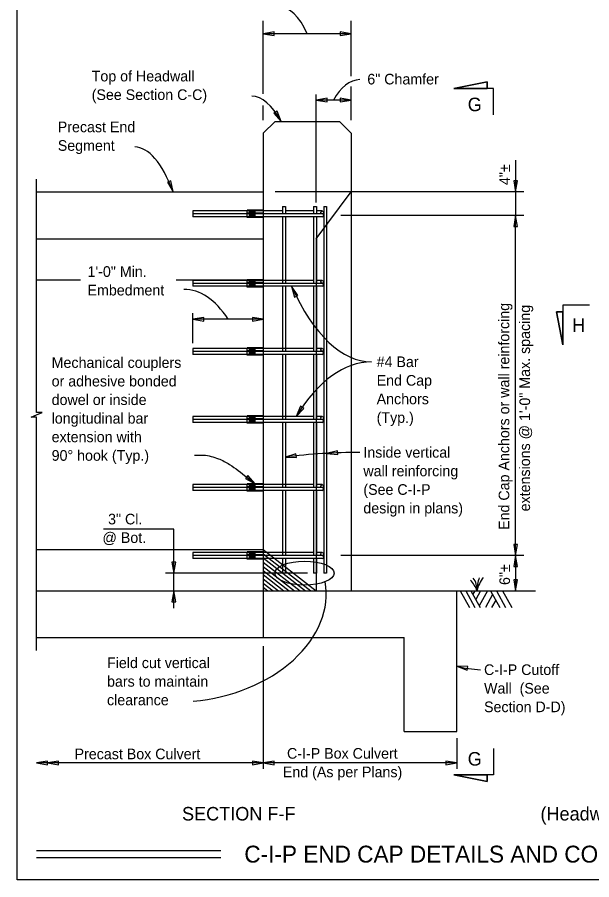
# Model space of a CAD drawing. Extents: x 0 to 30.8, y 0 to 19.8.
# Drawn here: x 0 to 8.16, y 0 to 12.25 of the extents above; entities that cross this region are included whole.
import ezdxf

# ---------------------------------------------------------------- set-up
doc = ezdxf.new("R2010")
doc.units = 0
for name, color, linetype in [('Dimension', 7, 'Continuous'), ('Miscellaneous', 7, 'Continuous'), ('Miscellaneous1', 7, 'Continuous'), ('Rebar', 7, 'Continuous'), ('SubStrConc', 7, 'Continuous'), ('SubStrConc_h', 7, 'Continuous'), ('TextStructures', 7, 'Continuous')]:
    doc.layers.add(name, color=color, linetype=linetype)

msp = doc.modelspace()

# ---------------------------------------------------------------- linework, layer by layer
at = {"layer": 'Dimension'}
for p, q in [((3.497, 11.165), (3.497, 12.205)), ((4.747, 11.419), (4.747, 12.205)), ((4.747, 12.021), (3.497, 12.021)), ((6.207, 11.244), (6.676, 11.338)), ((6.676, 11.338), (6.676, 11.244)), ((4.247, 9.625), (4.247, 11.159)), ((4.747, 10.791), (4.747, 11.27)), ((6.77, 11.244), (6.207, 11.244)), ((6.77, 10.869), (6.77, 11.244)), ((4.747, 11.078), (4.247, 11.078)), ((3.497, 10.791), (3.497, 11)), ((7.082, 10.226), (7.082, 9.773)), ((7.2, 9.773), (3.666, 9.773)), ((7.082, 9.773), (7.082, 9.44)), ((7.2, 9.44), (4.599, 9.44)), ((7.082, 4.607), (7.082, 9.44)), ((8.131, 8.162), (7.756, 8.162)), ((7.756, 8.162), (7.756, 7.6)), ((2.497, 7.625), (2.497, 8.052)), ((7.756, 7.6), (7.662, 8.068)), ((7.662, 8.068), (7.756, 8.068)), ((3.497, 7.965), (2.497, 7.965)), ((2.225, 4.982), (1.228, 4.982)), ((2.225, 4.357), (2.225, 4.982)), ((7.2, 4.607), (4.599, 4.607)), ((7.082, 4.607), (7.082, 4.107)), ((4.124, 4.357), (2.109, 4.357)), ((2.225, 4.107), (2.225, 4.357)), ((2.225, 3.857), (2.225, 4.107)), ((3.497, 3.319), (3.497, 1.578)), ((6.247, 2.013), (6.247, 1.578)), ((6.77, 1.865), (6.77, 1.49)), ((3.497, 1.661), (0.275, 1.661)), ((6.247, 1.661), (3.497, 1.661)), ((6.77, 1.49), (6.207, 1.49)), ((6.207, 1.49), (6.676, 1.396)), ((6.676, 1.396), (6.676, 1.49)), ((0.275, 0.414), (2.892, 0.414)), ((0.275, 0.314), (2.892, 0.314))]:
    msp.add_line(p, q, dxfattribs=at)
for points in [[(3.497, 12.02), (3.653, 11.994), (3.653, 12.047)], [(4.747, 12.02), (4.591, 12.047), (4.591, 11.994)], [(6.676, 11.244), (6.676, 11.338), (6.207, 11.244)], [(4.247, 11.078), (4.403, 11.051), (4.403, 11.104)], [(4.747, 11.078), (4.591, 11.104), (4.591, 11.051)], [(3.752, 10.773), (3.692, 10.92), (3.647, 10.892)], [(2.215, 9.773), (2.184, 9.929), (2.135, 9.91)], [(7.082, 9.773), (7.109, 9.93), (7.056, 9.93)], [(7.082, 9.44), (7.056, 9.284), (7.109, 9.284)], [(3.897, 8.432), (3.941, 8.279), (3.988, 8.302)], [(2.497, 7.965), (2.653, 7.938), (2.653, 7.991)], [(3.497, 7.965), (3.341, 7.991), (3.341, 7.938)], [(7.756, 8.068), (7.662, 8.068), (7.756, 7.6)], [(3.964, 6.582), (4.071, 6.698), (4.026, 6.727)], [(3.81, 6.004), (3.968, 5.998), (3.961, 6.05)], [(4.397, 6.058), (4.554, 6.04), (4.551, 6.093)], [(3.382, 5.625), (3.276, 5.743), (3.243, 5.701)], [(7.082, 4.607), (7.109, 4.763), (7.056, 4.763)], [(7.082, 4.607), (7.056, 4.451), (7.109, 4.451)], [(2.225, 4.357), (2.252, 4.513), (2.199, 4.513)], [(7.082, 4.107), (7.109, 4.263), (7.056, 4.263)], [(2.225, 4.107), (2.199, 3.951), (2.252, 3.951)], [(6.247, 3.036), (6.395, 2.978), (6.405, 3.03)], [(0.275, 1.661), (0.431, 1.634), (0.431, 1.687)], [(0.431, 1.661), (0.587, 1.634), (0.587, 1.687)], [(3.497, 1.66), (3.341, 1.687), (3.341, 1.634)], [(3.497, 1.66), (3.653, 1.634), (3.653, 1.687)], [(6.247, 1.66), (6.091, 1.687), (6.091, 1.634)], [(6.676, 1.49), (6.676, 1.396), (6.207, 1.49)]]:
    msp.add_lwpolyline(points, close=True, dxfattribs=at)
msp.add_lwpolyline([(0.275, 3.259), (0.275, 6.573), (0.197, 6.573), (0.275, 6.607), (0.352, 6.641), (0.275, 6.641), (0.275, 9.954)], dxfattribs=at)
for centre, radius, start, end in [((4.824, -1.734), 7.804, 89.6845, 97.4662), ((6.723, 4.952), 1.975, 256.0571, 265.9161)]:
    msp.add_arc(centre, radius, start, end, dxfattribs=at)
for centre, major_axis, ratio, start_param, end_param in [((3.768, 10.977), (0.045, -1.424), 0.393454, 2.379989, 3.141593), ((4.904, 10.391), (0.035, -0.978), 0.560741, 3.141593, 3.913766), ((3.249, 7.176), (-0.084, -3.958), 0.261149, 2.716835, 3.141593), ((1.586, 6.454), (-0.084, -3.958), 0.261149, 2.571065, 3.141593), ((2.421, 6.457), (0.052, -1.93), 0.503079, 2.454108, 3.141593), ((5.002, 11.557), (-0.033, 4.197), 0.40152, 2.407456, 3.141215), ((5.062, 3.46), (0.027, -3.9), 0.462577, 3.141946, 3.780946), ((2.532, 3.88), (-1.843, -0.35), 0.707446, 1.420997, 3.145082)]:
    msp.add_ellipse(centre, major_axis=major_axis, ratio=ratio, start_param=start_param, end_param=end_param, dxfattribs=at)
msp.add_ellipse((4.083, 4.357), major_axis=(0.421, 0), ratio=0.404515, dxfattribs=at)
msp.add_spline([(2.519, 6.033), (2.648, 6.033), (2.859, 5.982), (3.017, 5.901), (3.14, 5.816), (3.382, 5.625)], degree=3, dxfattribs=at)
at = {"layer": 'Miscellaneous'}
for p, q in [((3.497, 9.513), (3.268, 9.513)), ((3.497, 9.471), (3.268, 9.471)), ((3.34, 9.503), (3.3, 9.503)), ((3.3, 9.471), (3.3, 9.503)), ((3.34, 9.461), (3.3, 9.461)), ((3.3, 9.419), (3.3, 9.461)), ((3.34, 9.461), (3.3, 9.461)), ((3.31, 9.471), (3.31, 9.503)), ((3.31, 9.419), (3.31, 9.461)), ((3.32, 9.471), (3.32, 9.503)), ((3.32, 9.419), (3.32, 9.461)), ((3.33, 9.471), (3.33, 9.503)), ((3.33, 9.419), (3.33, 9.461)), ((3.38, 9.503), (3.34, 9.503)), ((3.34, 9.471), (3.34, 9.503)), ((3.38, 9.461), (3.34, 9.461)), ((3.34, 9.419), (3.34, 9.461)), ((3.38, 9.461), (3.34, 9.461)), ((3.35, 9.471), (3.35, 9.503)), ((3.35, 9.419), (3.35, 9.461)), ((3.36, 9.471), (3.36, 9.503)), ((3.36, 9.419), (3.36, 9.461)), ((3.37, 9.471), (3.37, 9.503)), ((3.37, 9.419), (3.37, 9.461)), ((3.38, 9.471), (3.38, 9.503)), ((3.38, 9.419), (3.38, 9.461)), ((3.497, 9.409), (3.268, 9.409)), ((3.34, 9.419), (3.3, 9.419)), ((3.38, 9.419), (3.34, 9.419)), ((3.497, 8.525), (3.268, 8.525)), ((3.497, 8.484), (3.268, 8.484)), ((3.34, 8.515), (3.3, 8.515)), ((3.3, 8.484), (3.3, 8.515)), ((3.34, 8.474), (3.3, 8.474)), ((3.3, 8.432), (3.3, 8.474)), ((3.34, 8.473), (3.3, 8.473)), ((3.31, 8.484), (3.31, 8.515)), ((3.31, 8.432), (3.31, 8.474)), ((3.32, 8.484), (3.32, 8.515)), ((3.32, 8.432), (3.32, 8.474)), ((3.33, 8.484), (3.33, 8.515)), ((3.33, 8.432), (3.33, 8.474)), ((3.38, 8.515), (3.34, 8.515)), ((3.34, 8.484), (3.34, 8.515)), ((3.38, 8.474), (3.34, 8.474)), ((3.34, 8.432), (3.34, 8.474)), ((3.38, 8.473), (3.34, 8.473)), ((3.35, 8.484), (3.35, 8.515)), ((3.35, 8.432), (3.35, 8.474)), ((3.36, 8.484), (3.36, 8.515)), ((3.36, 8.432), (3.36, 8.474)), ((3.37, 8.484), (3.37, 8.515)), ((3.37, 8.432), (3.37, 8.474)), ((3.38, 8.484), (3.38, 8.515)), ((3.38, 8.432), (3.38, 8.474)), ((3.497, 8.422), (3.268, 8.422)), ((3.34, 8.432), (3.3, 8.432)), ((3.38, 8.432), (3.34, 8.432)), ((3.497, 7.559), (3.268, 7.559)), ((3.497, 7.517), (3.268, 7.517)), ((3.34, 7.549), (3.3, 7.549)), ((3.3, 7.517), (3.3, 7.549)), ((3.34, 7.507), (3.3, 7.507)), ((3.3, 7.465), (3.3, 7.507)), ((3.34, 7.507), (3.3, 7.507)), ((3.31, 7.517), (3.31, 7.549)), ((3.31, 7.465), (3.31, 7.507)), ((3.32, 7.517), (3.32, 7.549)), ((3.32, 7.465), (3.32, 7.507)), ((3.33, 7.517), (3.33, 7.549)), ((3.33, 7.465), (3.33, 7.507)), ((3.38, 7.549), (3.34, 7.549)), ((3.34, 7.517), (3.34, 7.549)), ((3.38, 7.507), (3.34, 7.507)), ((3.34, 7.465), (3.34, 7.507)), ((3.38, 7.507), (3.34, 7.507)), ((3.35, 7.517), (3.35, 7.549)), ((3.35, 7.465), (3.35, 7.507)), ((3.36, 7.517), (3.36, 7.549)), ((3.36, 7.465), (3.36, 7.507)), ((3.37, 7.517), (3.37, 7.549)), ((3.37, 7.465), (3.37, 7.507)), ((3.38, 7.517), (3.38, 7.549)), ((3.38, 7.465), (3.38, 7.507)), ((3.497, 7.455), (3.268, 7.455)), ((3.34, 7.465), (3.3, 7.465)), ((3.38, 7.465), (3.34, 7.465)), ((3.497, 6.592), (3.268, 6.592)), ((3.497, 6.55), (3.268, 6.55)), ((3.34, 6.582), (3.3, 6.582)), ((3.3, 6.55), (3.3, 6.582)), ((3.34, 6.54), (3.3, 6.54)), ((3.3, 6.499), (3.3, 6.54)), ((3.34, 6.54), (3.3, 6.54)), ((3.34, 6.499), (3.3, 6.499)), ((3.31, 6.55), (3.31, 6.582)), ((3.31, 6.499), (3.31, 6.54)), ((3.32, 6.55), (3.32, 6.582)), ((3.32, 6.499), (3.32, 6.54)), ((3.33, 6.55), (3.33, 6.582)), ((3.33, 6.499), (3.33, 6.54)), ((3.38, 6.582), (3.34, 6.582)), ((3.34, 6.55), (3.34, 6.582)), ((3.38, 6.54), (3.34, 6.54)), ((3.34, 6.499), (3.34, 6.54)), ((3.38, 6.54), (3.34, 6.54)), ((3.38, 6.499), (3.34, 6.499)), ((3.35, 6.55), (3.35, 6.582)), ((3.35, 6.499), (3.35, 6.54)), ((3.36, 6.55), (3.36, 6.582)), ((3.36, 6.499), (3.36, 6.54)), ((3.37, 6.55), (3.37, 6.582)), ((3.37, 6.499), (3.37, 6.54)), ((3.38, 6.55), (3.38, 6.582)), ((3.38, 6.499), (3.38, 6.54)), ((3.497, 6.488), (3.268, 6.488)), ((3.497, 5.625), (3.268, 5.625)), ((3.497, 5.584), (3.268, 5.584)), ((3.497, 5.522), (3.268, 5.522)), ((3.34, 5.615), (3.3, 5.615)), ((3.3, 5.584), (3.3, 5.615)), ((3.34, 5.574), (3.3, 5.574)), ((3.3, 5.532), (3.3, 5.574)), ((3.34, 5.573), (3.3, 5.573)), ((3.34, 5.532), (3.3, 5.532)), ((3.31, 5.584), (3.31, 5.615)), ((3.31, 5.532), (3.31, 5.574)), ((3.32, 5.584), (3.32, 5.615)), ((3.32, 5.532), (3.32, 5.574)), ((3.33, 5.584), (3.33, 5.615)), ((3.33, 5.532), (3.33, 5.574)), ((3.38, 5.615), (3.34, 5.615)), ((3.34, 5.584), (3.34, 5.615)), ((3.38, 5.574), (3.34, 5.574)), ((3.34, 5.532), (3.34, 5.574)), ((3.38, 5.573), (3.34, 5.573)), ((3.38, 5.532), (3.34, 5.532)), ((3.35, 5.584), (3.35, 5.615)), ((3.35, 5.532), (3.35, 5.574)), ((3.36, 5.584), (3.36, 5.615)), ((3.36, 5.532), (3.36, 5.574)), ((3.37, 5.584), (3.37, 5.615)), ((3.37, 5.532), (3.37, 5.574)), ((3.38, 5.584), (3.38, 5.615)), ((3.38, 5.532), (3.38, 5.574)), ((3.497, 4.659), (3.268, 4.659)), ((3.497, 4.617), (3.268, 4.617)), ((3.497, 4.555), (3.268, 4.555)), ((3.34, 4.649), (3.3, 4.649)), ((3.3, 4.617), (3.3, 4.649)), ((3.34, 4.607), (3.3, 4.607)), ((3.3, 4.565), (3.3, 4.607)), ((3.34, 4.607), (3.3, 4.607)), ((3.34, 4.565), (3.3, 4.565)), ((3.31, 4.617), (3.31, 4.649)), ((3.31, 4.565), (3.31, 4.607)), ((3.32, 4.617), (3.32, 4.649)), ((3.32, 4.565), (3.32, 4.607)), ((3.33, 4.617), (3.33, 4.649)), ((3.33, 4.565), (3.33, 4.607)), ((3.38, 4.649), (3.34, 4.649)), ((3.34, 4.617), (3.34, 4.649)), ((3.38, 4.607), (3.34, 4.607)), ((3.34, 4.565), (3.34, 4.607)), ((3.38, 4.607), (3.34, 4.607)), ((3.38, 4.565), (3.34, 4.565)), ((3.35, 4.617), (3.35, 4.649)), ((3.35, 4.565), (3.35, 4.607)), ((3.36, 4.617), (3.36, 4.649)), ((3.36, 4.565), (3.36, 4.607)), ((3.37, 4.617), (3.37, 4.649)), ((3.37, 4.565), (3.37, 4.607)), ((3.38, 4.617), (3.38, 4.649)), ((3.38, 4.565), (3.38, 4.607)), ((6.247, 4.107), (7.366, 4.107)), ((6.296, 4.107), (6.427, 3.867)), ((6.374, 4.107), (6.505, 3.867)), ((6.448, 4.107), (6.579, 3.867)), ((6.503, 4.107), (6.476, 4.057)), ((6.583, 4.107), (6.516, 3.984)), ((6.683, 4.107), (6.565, 3.893)), ((6.756, 4.054), (6.654, 3.867)), ((6.727, 4.107), (6.859, 3.867)), ((6.81, 4.107), (6.941, 3.867)), ((6.898, 4.107), (7.03, 3.867)), ((6.8, 3.973), (6.742, 3.867))]:
    msp.add_line(p, q, dxfattribs=at)
for points in [[(3.268, 9.471), (3.268, 9.513)], [(3.268, 9.409), (3.268, 9.471)], [(3.268, 8.484), (3.268, 8.525)], [(3.268, 8.422), (3.268, 8.484)], [(3.268, 7.517), (3.268, 7.559)], [(3.268, 7.455), (3.268, 7.517)], [(3.268, 6.55), (3.268, 6.592)], [(3.268, 6.488), (3.268, 6.55)], [(3.268, 5.584), (3.268, 5.625)], [(3.268, 5.522), (3.268, 5.584)], [(3.268, 4.617), (3.268, 4.659)], [(3.268, 4.555), (3.268, 4.617)]]:
    msp.add_lwpolyline(points, dxfattribs=at)
for centre, radius, start, end in [((7.096, 3.956), 0.584, 144.3747, 165.0402), ((6.935, 4.127), 0.403, 155.9437, 182.9219), ((6.205, 4.007), 0.342, 16.9178, 46.7762), ((6.261, 4.126), 0.272, 356.0505, 36.015)]:
    msp.add_arc(centre, radius, start, end, dxfattribs=at)
at = {"layer": 'Miscellaneous1'}
msp.add_lwpolyline([(0, 19.8), (30.8, 19.8), (30.8, 0), (0, 0)], close=True, dxfattribs=at)
at = {"layer": 'Rebar'}
for p, q in [((3.768, 9.565), (3.768, 9.461)), ((3.768, 9.565), (3.81, 9.565)), ((3.81, 9.565), (3.81, 9.461)), ((4.21, 9.565), (4.21, 9.461)), ((4.21, 9.565), (4.251, 9.565)), ((4.251, 9.565), (4.251, 9.461)), ((4.355, 9.565), (4.397, 9.565)), ((4.355, 9.565), (4.355, 4.357)), ((4.397, 9.565), (4.397, 4.357)), ((2.497, 9.503), (2.497, 9.419)), ((3.768, 9.503), (2.497, 9.503)), ((4.334, 9.461), (2.497, 9.461)), ((4.21, 9.503), (3.81, 9.503)), ((4.334, 9.503), (4.251, 9.503)), ((4.334, 9.419), (2.497, 9.419)), ((3.768, 9.419), (3.768, 8.473)), ((3.81, 9.417), (3.81, 8.473)), ((4.21, 9.419), (4.21, 8.474)), ((4.251, 9.417), (4.251, 8.474)), ((2.497, 8.515), (2.497, 8.432)), ((4.21, 8.515), (2.497, 8.515)), ((4.334, 8.474), (2.497, 8.474)), ((4.334, 8.515), (4.251, 8.515)), ((4.334, 8.432), (2.497, 8.432)), ((3.768, 8.432), (3.768, 7.507)), ((3.81, 8.432), (3.81, 7.507)), ((4.21, 8.432), (4.21, 7.507)), ((4.251, 8.432), (4.251, 7.507)), ((2.497, 7.548), (2.497, 7.465)), ((4.21, 7.548), (2.497, 7.548)), ((4.334, 7.507), (2.497, 7.507)), ((4.334, 7.548), (4.251, 7.548)), ((4.334, 7.465), (2.497, 7.465)), ((3.768, 7.465), (3.768, 6.54)), ((3.81, 7.465), (3.81, 6.54)), ((4.21, 7.465), (4.21, 6.54)), ((4.251, 7.465), (4.251, 6.54)), ((2.497, 6.582), (2.497, 6.499)), ((4.21, 6.582), (2.497, 6.582)), ((4.334, 6.54), (2.497, 6.54)), ((4.334, 6.499), (2.497, 6.499)), ((3.768, 6.499), (3.768, 5.573)), ((3.81, 6.499), (3.81, 5.573)), ((4.21, 6.499), (4.21, 5.574)), ((4.334, 6.582), (4.251, 6.582)), ((4.251, 6.499), (4.251, 5.574)), ((2.497, 5.615), (2.497, 5.532)), ((4.21, 5.615), (2.497, 5.615)), ((4.334, 5.574), (2.497, 5.574)), ((4.334, 5.532), (2.497, 5.532)), ((3.768, 5.532), (3.768, 4.607)), ((3.81, 5.532), (3.81, 4.607)), ((4.21, 5.532), (4.21, 4.607)), ((4.334, 5.615), (4.251, 5.615)), ((4.251, 5.532), (4.251, 4.607)), ((2.497, 4.648), (2.497, 4.565)), ((4.21, 4.648), (2.497, 4.648)), ((4.334, 4.607), (2.497, 4.607)), ((4.334, 4.565), (2.497, 4.565)), ((3.768, 4.565), (3.768, 4.357)), ((3.81, 4.565), (3.81, 4.357)), ((4.21, 4.565), (4.21, 4.357)), ((4.334, 4.648), (4.251, 4.648)), ((4.251, 4.565), (4.251, 4.357)), ((3.81, 4.357), (3.768, 4.357)), ((4.251, 4.357), (4.21, 4.357)), ((4.397, 4.357), (4.355, 4.357))]:
    msp.add_line(p, q, dxfattribs=at)
for centre in [(4.334, 9.482), (4.334, 8.494), (4.334, 7.528), (4.334, 6.561), (4.334, 5.594), (4.334, 4.628)]:
    msp.add_circle(centre, 0.0208, dxfattribs=at)
for centre in [(4.334, 9.44), (4.334, 8.453), (4.334, 7.486), (4.334, 6.519), (4.334, 5.553), (4.334, 4.586)]:
    msp.add_arc(centre, 0.0208, 270, 90, dxfattribs=at)
at = {"layer": 'SubStrConc'}
for p, q in [((3.664, 10.773), (3.497, 10.607)), ((3.664, 10.773), (4.58, 10.773)), ((4.747, 10.607), (4.58, 10.773)), ((3.497, 10.607), (3.497, 4.107)), ((4.747, 10.607), (4.747, 4.107)), ((4.247, 9.107), (4.747, 9.773)), ((4.247, 9.107), (4.247, 4.107)), ((3.497, 4.69), (4.247, 4.107)), ((3.497, 4.631), (4.171, 4.107)), ((3.497, 4.572), (4.095, 4.107)), ((3.497, 4.512), (4.019, 4.107)), ((3.497, 4.453), (3.942, 4.107)), ((3.497, 4.394), (3.866, 4.107)), ((3.497, 4.335), (3.79, 4.107)), ((3.497, 4.275), (3.714, 4.107)), ((3.497, 4.216), (3.638, 4.107)), ((3.497, 4.157), (3.561, 4.107)), ((3.497, 4.107), (4.747, 4.107))]:
    msp.add_line(p, q, dxfattribs=at)
at = {"layer": 'SubStrConc_h'}
for p, q in [((0.275, 9.773), (3.497, 9.773)), ((0.275, 9.107), (3.497, 9.107)), ((0.275, 8.524), (0.898, 8.524)), ((2.259, 8.524), (3.497, 8.524)), ((0.275, 4.69), (3.497, 4.69)), ((0.275, 4.107), (3.497, 4.107)), ((3.497, 4.107), (3.497, 3.44)), ((4.747, 4.107), (6.247, 4.107)), ((6.247, 2.107), (6.247, 4.107)), ((0.275, 3.44), (5.497, 3.44)), ((5.497, 2.107), (5.497, 3.44)), ((5.497, 2.107), (6.247, 2.107))]:
    msp.add_line(p, q, dxfattribs=at)
at = {"layer": 'TextStructures'}
msp.add_lwpolyline([(0, 19.477), (30.8, 19.477), (30.8, 0), (0, 0)], close=True, dxfattribs=at)

# ---------------------------------------------------------------- texts
at = {"layer": 'Dimension'}
for s, p in [('Top of Headwall', (1.058, 11.343)), ('(See Section C-C)', (1.058, 11.079)), ('Precast End', (0.576, 10.621)), ('Segment', (0.576, 10.357)), ('1\'-0" Min.', (0.999, 8.566)), ('Embedment', (0.999, 8.302)), ('Mechanical couplers', (0.489, 7.273)), ('#4 Bar', (5.108, 7.284)), ('or adhesive bonded', (0.489, 7.009)), ('End Cap', (5.108, 7.02)), ('dowel or inside', (0.489, 6.745)), ('Anchors', (5.108, 6.756)), ('longitudinal bar', (0.489, 6.481)), ('(Typ.)', (5.108, 6.492)), ('extension with', (0.489, 6.217)), ('Inside vertical', (4.919, 5.997)), ('90° hook (Typ.)', (0.489, 5.953)), ('wall reinforcing', (4.919, 5.733)), ('(See C-I-P', (4.919, 5.469)), ('design in plans)', (4.919, 5.205)), ('3" Cl.', (1.291, 5.049)), ('@ Bot.', (1.211, 4.785)), ('Field cut vertical', (1.276, 3.007)), ('C-I-P Cutoff', (6.634, 2.909)), ('bars to maintain', (1.276, 2.743)), ('Wall  (See', (6.634, 2.645)), ('clearance', (1.276, 2.479)), ('Section D-D)', (6.634, 2.381)), ('C-I-P Box Culvert', (3.834, 1.72)), ('End (As per Plans)', (3.775, 1.456))]:
    msp.add_text(s, height=0.1512, dxfattribs=at).set_placement(p)
for s, p in [('End Cap Anchors or wall reinforcing', (6.993, 4.971)), ('extensions @ 1\'-0" Max. spacing', (7.288, 5.234))]:
    msp.add_text(s, height=0.1512, rotation=90, dxfattribs=at).set_placement(p)
at = {"layer": 'TextStructures'}
for s, height, p in [('6" Chamfer', 0.1512, (4.975, 11.3)), ('G', 0.192, (6.402, 10.92)), ('H', 0.192, (7.886, 7.785)), ('Precast Box Culvert', 0.1512, (0.815, 1.712)), ('G', 0.192, (6.402, 1.622)), ('SECTION F-F', 0.192, (2.342, 0.842)), ('(Headwall, Toe Slab and Cutoff Wall Reinforcing not shown for clarity)', 0.192, (7.436, 0.842)), ('C-I-P END CAP DETAILS AND CONNECTION TO PRECAST BOX', 0.24, (3.227, 0.244))]:
    msp.add_text(s, height=height, dxfattribs=at).set_placement(p)
for s, p in [('4"±', (7.003, 9.87)), ('6"±', (7.003, 4.188))]:
    msp.add_text(s, height=0.1512, rotation=90, dxfattribs=at).set_placement(p)

doc.saveas('drawing.dxf')
